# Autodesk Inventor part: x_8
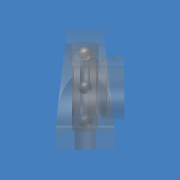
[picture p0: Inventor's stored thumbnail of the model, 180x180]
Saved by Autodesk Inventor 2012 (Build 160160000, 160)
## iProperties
Company: CAD-Verlag
Part Number: x_8
Document SubType Name: Modeling
Created: 2004-09
Material: Standard
Designer: Greiling
Manufacturer: Standard
Standards Organization: Custom
Density: 1 g/cm^3
Control State: 0
Master: False
Checked Out: False
Shininess: 64.0
Length Units: 11269
Angle Units: 11279
Time Units: 11290
Mass Units: 11283
Length Display Precision: 3
Angle Display Precision: 2
Compacted: True
Übersetzungsnorm: STEP AP214CD
Dateiname: w2c22665.stp
Vorprozessor: ACIS
Postprozessor: Build: 081d, Release: 8 SP1 - Date: Tue 01/26/2004
Gesendete Einheiten: MILLIMETERS
Unbestimmtheit: 1e-06
Density: 0.0
Volumn: 0.0
Area: 0.0
PropertySet Name: Model Information
Author: Jürgen Kronas
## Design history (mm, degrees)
feature "Basis1"
node "Volumenkörper1"
node "Volumenkörpern"
node "Oberflächenkörpern"
